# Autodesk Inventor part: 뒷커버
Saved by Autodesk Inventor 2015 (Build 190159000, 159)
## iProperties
Created: 2025-06
Part Number: 뒷커버
Material: 일반
Document SubType Name: Modeling
Designer: User
Density: 1 g/cm^3
Appearance: 기본값
Author: User
Author: jhkim
Creation Date: 2025-05-23
Sending System: Autodesk Inventor 2026
Preprocessor: ST-DEVELOPER v20.1
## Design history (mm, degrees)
node "뒷커버1"
node "솔리드1"
node "기준1"
